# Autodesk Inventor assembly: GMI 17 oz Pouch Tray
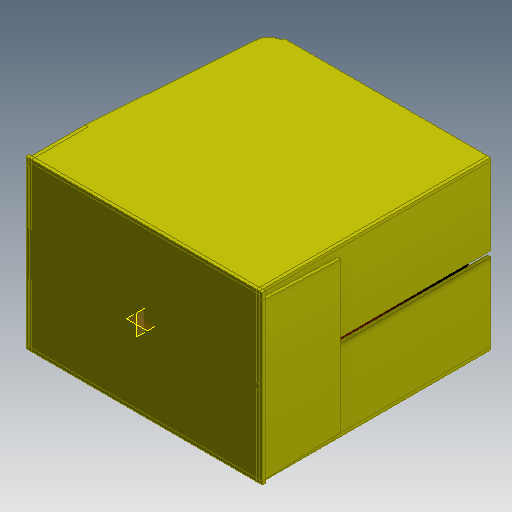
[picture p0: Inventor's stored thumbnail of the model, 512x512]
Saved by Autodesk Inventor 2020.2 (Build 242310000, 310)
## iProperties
Created: 1999-11
Part Number: GMI 17 oz Pouch Tray
Document SubType Name: Assembly
Designer: sspink
Mass: 570.322 g
Surface Area: 3951.57 cm^2
Volume: 570.322 cm^3
Density: 1 g/cm^3
Control State: 0
Checked Out: False
Last Check In By: gpurviance
Last Check In Date: 2000-01-06
Master: False
Shininess: 0.0
Length Units: 11269
Angle Units: 11279
Time Units: 11290
Mass Units: 11283
Length Display Precision: 3
Angle Display Precision: 2
Compacted: True
Dimensions: 159x220,5x225,5 mm
Mass: 0,57 kg
DocNumber: GMI 17 oz Pouch Tray.iam
Folder: 01 - Themengebiete\Simplification\01 - Packaging machine\
VDS_Category: 3D Komponenten
Density: 0.0
Volumn: 0.0
Area: 0.0
PropertySet Name: Model Information
Author: sspink
Revision Number: -
Title: product
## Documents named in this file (8)
- D:\07 - DEMODATEN\OTX 2019 - Dataset - UPDATE - Dez2019\Designs\07-Packing machine\GMI 17 oz Pouch Tray.iam
- D:\07 - DEMODATEN\OTX 2019 - Dataset - UPDATE - Dez2019\Designs\07-Packing machine\Parts\ADSK-011837.ipt
- D:\07 - DEMODATEN\OTX 2019 - Dataset - UPDATE - Dez2019\Designs\07-Packing machine\Parts\ADSK-011828.ipt
- D:\07 - DEMODATEN\OTX 2019 - Dataset - UPDATE - Dez2019\Designs\07-Packing machine\Parts\ADSK-011831.ipt
- D:\07 - DEMODATEN\OTX 2019 - Dataset - UPDATE - Dez2019\Designs\07-Packing machine\Parts\ADSK-011829.ipt
- D:\07 - DEMODATEN\OTX 2019 - Dataset - UPDATE - Dez2019\Designs\07-Packing machine\Parts\ADSK-011838.ipt
- D:\07 - DEMODATEN\OTX 2019 - Dataset - UPDATE - Dez2019\Designs\07-Packing machine\Parts\ADSK-011832.ipt
- D:\07 - DEMODATEN\OTX 2019 - Dataset - UPDATE - Dez2019\Designs\07-Packing machine\Parts\ADSK-011830.ipt
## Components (15 placed, 7 different names)
1. ADSK-011828:1 — Mate:1, Mate:2, Angular1, Mate:4, Mate:8, Mate:9, Flush:3, Flush:4, Angular2, Mate:10, Angular3, Angular8, Fluchtend:17, Fluchtend:18, Fluchtend:19
2. ADSK-011829:1 — Mate:4, Mate:9, Angular8
3. ADSK-011831:1 — Mate:3, Flush:1, Angular4
4. ADSK-011832:1 — Mate:8, Mate:10, Angular3
5. ADSK-011837:1 — Mate:1, Mate:3, Flush:1, Mate:5, Flush:4, Angular2, Flush:5, Angular4, Angular7
6. ADSK-011838:1 — Mate:6, Flush:6, Angular6
7. ADSK-011838:2 — Mate:5, Flush:5, Angular7
8. ADSK-011831:2 — Mate:7, Flush:2, Angular5
9. ADSK-011837:2 — Mate:2, Angular1, Mate:6, Mate:7, Flush:2, Flush:3, Flush:6, Angular5, Angular6
10. ADSK-011830:1 — Passend:23, Passend:24, Passend:25
11. ADSK-011830:2
12. ADSK-011830:3
13. ADSK-011830:4
14. ADSK-011830:5
15. ADSK-011830:6
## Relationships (30: Mate 13, Flush 9, Angle 8)
- Mate:1: ADSK-011828:1 ↔ ADSK-011837:1
- Mate:2: ADSK-011828:1 ↔ ADSK-011837:2
- Angular1 [Angle]: ADSK-011828:1 ↔ ADSK-011837:2
- Mate:3: ADSK-011831:1 ↔ ADSK-011837:1
- Flush:1: ADSK-011831:1 ↔ ADSK-011837:1
- Mate:4: ADSK-011828:1 ↔ ADSK-011829:1
- Mate:5: ADSK-011837:1 ↔ ADSK-011838:2
- Mate:6: ADSK-011838:1 ↔ ADSK-011837:2
- Mate:7: ADSK-011831:2 ↔ ADSK-011837:2
- Flush:2: ADSK-011831:2 ↔ ADSK-011837:2
- Mate:8: ADSK-011828:1 ↔ ADSK-011832:1
- Mate:9: ADSK-011828:1 ↔ ADSK-011829:1
- Flush:3: ADSK-011828:1 ↔ ADSK-011837:2
- Flush:4: ADSK-011828:1 ↔ ADSK-011837:1
- Angular2 [Angle]: ADSK-011828:1 ↔ ADSK-011837:1
- Flush:5: ADSK-011837:1 ↔ ADSK-011838:2
- Flush:6: ADSK-011838:1 ↔ ADSK-011837:2
- Mate:10: ADSK-011828:1 ↔ ADSK-011832:1
- Angular3 [Angle]: ADSK-011828:1 ↔ ADSK-011832:1
- Angular4 [Angle]: ADSK-011831:1 ↔ ADSK-011837:1
- Angular5 [Angle]: ADSK-011831:2 ↔ ADSK-011837:2
- Angular6 [Angle]: ADSK-011838:1 ↔ ADSK-011837:2
- Angular7 [Angle]: ADSK-011837:1 ↔ ADSK-011838:2
- Angular8 [Angle]: ADSK-011828:1 ↔ ADSK-011829:1
- Fluchtend:17 [Flush]: ADSK-011828:1
- Fluchtend:18 [Flush]: ADSK-011828:1
- Fluchtend:19 [Flush]: ADSK-011828:1
- Passend:23 [Mate]: ADSK-011830:1
- Passend:24 [Mate]: ADSK-011830:1
- Passend:25 [Mate]: ADSK-011830:1
